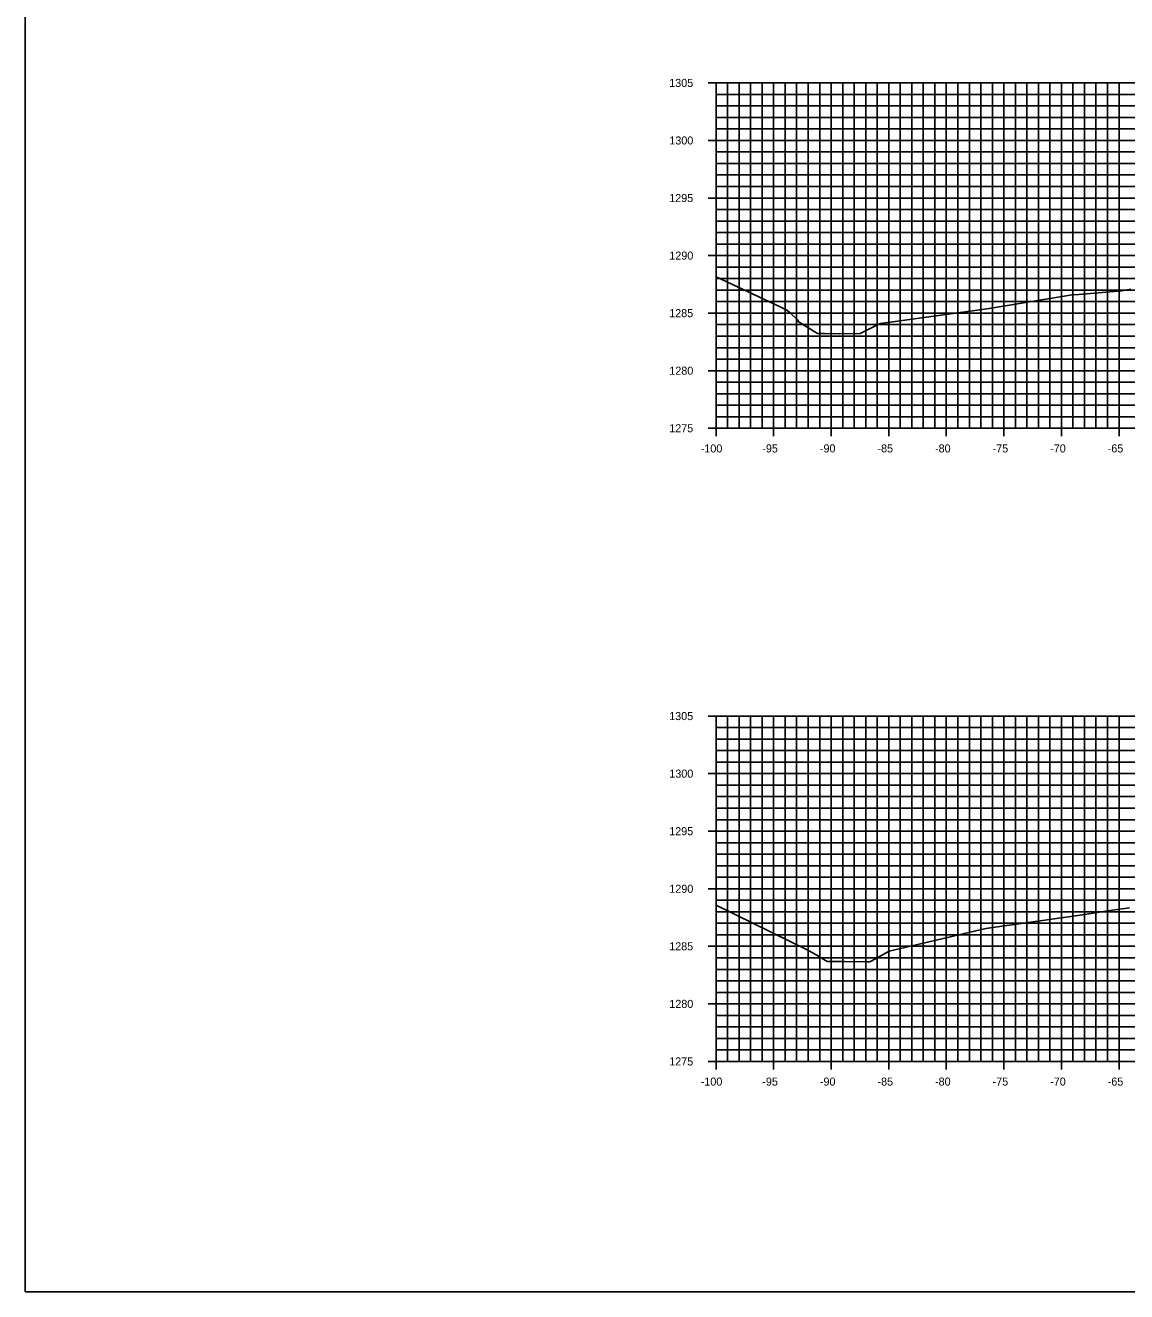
# Model space of a CAD drawing. Extents: x 674939 to 678919, y 750652 to 765176.
# Drawn here: x 678578.5 to 678674.2, y 755292.6 to 755402.6 of the extents above; entities that cross this region are included whole.
import ezdxf

# ---------------------------------------------------------------- set-up
doc = ezdxf.new("R2010")
doc.units = 0
for name, color, linetype in [('Level 10', 7, 'Continuous'), ('Level 20', 7, 'Continuous'), ('Level 4', 7, 'Continuous'), ('Level 8', 7, 'Continuous'), ('Level 9', 7, 'Continuous')]:
    doc.layers.add(name, color=color, linetype=linetype)

msp = doc.modelspace()

# ---------------------------------------------------------------- linework, layer by layer
at = {"layer": 'Level 10'}
for points in [[(678638.53, 755380.69), (678644.09, 755378.11), (678644.62, 755377.85), (678644.67, 755377.82), (678644.99, 755377.54), (678645.59, 755376.97), (678645.72, 755376.77), (678645.74, 755376.76), (678647.33, 755375.79), (678647.95, 755375.78), (678649.25, 755375.76), (678649.29, 755375.76), (678651.04, 755375.79), (678652.72, 755376.62), (678652.73, 755376.63), (678652.81, 755376.64), (678661.86, 755377.89), (678662.24, 755377.94), (678669.46, 755379.13), (678670.03, 755379.18), (678673.75, 755379.49), (678673.79, 755379.5), (678674.56, 755379.62)], [(678638.53, 755326.12), (678646.63, 755322.17), (678647.23, 755321.8), (678648.19, 755321.24), (678648.79, 755321.23), (678649.7, 755321.22), (678651.65, 755321.2), (678651.85, 755321.2), (678651.99, 755321.27), (678653.58, 755322.14), (678661.95, 755324.09), (678662.17, 755324.14), (678662.56, 755324.19), (678670.35, 755325.28), (678672.77, 755325.65), (678674.43, 755325.89)]]:
    msp.add_lwpolyline(points, dxfattribs=at)
at = {"layer": 'Level 20'}
for p, q in [((678638.53, 755397.55), (678838.53, 755397.55)), ((678638.53, 755367.55), (678638.53, 755397.55)), ((678639.53, 755367.55), (678639.53, 755397.55)), ((678640.53, 755367.55), (678640.53, 755397.55)), ((678641.53, 755367.55), (678641.53, 755397.55)), ((678642.53, 755367.55), (678642.53, 755397.55)), ((678643.53, 755367.55), (678643.53, 755397.55)), ((678644.53, 755367.55), (678644.53, 755397.55)), ((678645.53, 755367.55), (678645.53, 755397.55)), ((678646.53, 755367.55), (678646.53, 755397.55)), ((678647.53, 755367.55), (678647.53, 755397.55)), ((678648.53, 755367.55), (678648.53, 755397.55)), ((678649.53, 755367.55), (678649.53, 755397.55)), ((678650.53, 755367.55), (678650.53, 755397.55)), ((678651.53, 755367.55), (678651.53, 755397.55)), ((678652.53, 755367.55), (678652.53, 755397.55)), ((678653.53, 755367.55), (678653.53, 755397.55)), ((678654.53, 755367.55), (678654.53, 755397.55)), ((678655.53, 755367.55), (678655.53, 755397.55)), ((678656.53, 755367.55), (678656.53, 755397.55)), ((678657.53, 755367.55), (678657.53, 755397.55)), ((678658.53, 755367.55), (678658.53, 755397.55)), ((678659.53, 755367.55), (678659.53, 755397.55)), ((678660.53, 755367.55), (678660.53, 755397.55)), ((678661.53, 755367.55), (678661.53, 755397.55)), ((678662.53, 755367.55), (678662.53, 755397.55)), ((678663.53, 755367.55), (678663.53, 755397.55)), ((678664.53, 755367.55), (678664.53, 755397.55)), ((678665.53, 755367.55), (678665.53, 755397.55)), ((678666.53, 755367.55), (678666.53, 755397.55)), ((678667.53, 755367.55), (678667.53, 755397.55)), ((678668.53, 755367.55), (678668.53, 755397.55)), ((678669.53, 755367.55), (678669.53, 755397.55)), ((678670.53, 755367.55), (678670.53, 755397.55)), ((678671.53, 755367.55), (678671.53, 755397.55)), ((678672.53, 755367.55), (678672.53, 755397.55)), ((678673.53, 755367.55), (678673.53, 755397.55)), ((678638.53, 755396.55), (678838.53, 755396.55)), ((678638.53, 755395.55), (678838.53, 755395.55)), ((678638.53, 755394.55), (678838.53, 755394.55)), ((678638.53, 755393.55), (678838.53, 755393.55)), ((678638.53, 755392.55), (678838.53, 755392.55)), ((678638.53, 755391.55), (678838.53, 755391.55)), ((678638.53, 755390.55), (678838.53, 755390.55)), ((678638.53, 755389.55), (678838.53, 755389.55)), ((678638.53, 755388.55), (678838.53, 755388.55)), ((678638.53, 755387.55), (678838.53, 755387.55)), ((678638.53, 755386.55), (678838.53, 755386.55)), ((678638.53, 755385.55), (678838.53, 755385.55)), ((678638.53, 755384.55), (678838.53, 755384.55)), ((678638.53, 755383.55), (678838.53, 755383.55)), ((678638.53, 755382.55), (678838.53, 755382.55)), ((678638.53, 755381.55), (678838.53, 755381.55)), ((678638.53, 755380.55), (678838.53, 755380.55)), ((678638.53, 755379.55), (678838.53, 755379.55)), ((678638.53, 755378.55), (678838.53, 755378.55)), ((678638.53, 755377.55), (678838.53, 755377.55)), ((678638.53, 755376.55), (678838.53, 755376.55)), ((678638.53, 755375.55), (678838.53, 755375.55)), ((678638.53, 755374.55), (678838.53, 755374.55)), ((678638.53, 755373.55), (678838.53, 755373.55)), ((678638.53, 755372.55), (678838.53, 755372.55)), ((678638.53, 755371.55), (678838.53, 755371.55)), ((678638.53, 755370.55), (678838.53, 755370.55)), ((678638.53, 755369.55), (678838.53, 755369.55)), ((678638.53, 755368.55), (678838.53, 755368.55)), ((678638.53, 755367.55), (678838.53, 755367.55)), ((678638.53, 755342.55), (678838.53, 755342.55)), ((678638.53, 755312.55), (678638.53, 755342.55)), ((678639.53, 755312.55), (678639.53, 755342.55)), ((678640.53, 755312.55), (678640.53, 755342.55)), ((678641.53, 755312.55), (678641.53, 755342.55)), ((678642.53, 755312.55), (678642.53, 755342.55)), ((678643.53, 755312.55), (678643.53, 755342.55)), ((678644.53, 755312.55), (678644.53, 755342.55)), ((678645.53, 755312.55), (678645.53, 755342.55)), ((678646.53, 755312.55), (678646.53, 755342.55)), ((678647.53, 755312.55), (678647.53, 755342.55)), ((678648.53, 755312.55), (678648.53, 755342.55)), ((678649.53, 755312.55), (678649.53, 755342.55)), ((678650.53, 755312.55), (678650.53, 755342.55)), ((678651.53, 755312.55), (678651.53, 755342.55)), ((678652.53, 755312.55), (678652.53, 755342.55)), ((678653.53, 755312.55), (678653.53, 755342.55)), ((678654.53, 755312.55), (678654.53, 755342.55)), ((678655.53, 755312.55), (678655.53, 755342.55)), ((678656.53, 755312.55), (678656.53, 755342.55)), ((678657.53, 755312.55), (678657.53, 755342.55)), ((678658.53, 755312.55), (678658.53, 755342.55)), ((678659.53, 755312.55), (678659.53, 755342.55)), ((678660.53, 755312.55), (678660.53, 755342.55)), ((678661.53, 755312.55), (678661.53, 755342.55)), ((678662.53, 755312.55), (678662.53, 755342.55)), ((678663.53, 755312.55), (678663.53, 755342.55)), ((678664.53, 755312.55), (678664.53, 755342.55)), ((678665.53, 755312.55), (678665.53, 755342.55)), ((678666.53, 755312.55), (678666.53, 755342.55)), ((678667.53, 755312.55), (678667.53, 755342.55)), ((678668.53, 755312.55), (678668.53, 755342.55)), ((678669.53, 755312.55), (678669.53, 755342.55)), ((678670.53, 755312.55), (678670.53, 755342.55)), ((678671.53, 755312.55), (678671.53, 755342.55)), ((678672.53, 755312.55), (678672.53, 755342.55)), ((678673.53, 755312.55), (678673.53, 755342.55)), ((678638.53, 755341.55), (678838.53, 755341.55)), ((678638.53, 755340.55), (678838.53, 755340.55)), ((678638.53, 755339.55), (678838.53, 755339.55)), ((678638.53, 755338.55), (678838.53, 755338.55)), ((678638.53, 755337.55), (678838.53, 755337.55)), ((678638.53, 755336.55), (678838.53, 755336.55)), ((678638.53, 755335.55), (678838.53, 755335.55)), ((678638.53, 755334.55), (678838.53, 755334.55)), ((678638.53, 755333.55), (678838.53, 755333.55)), ((678638.53, 755332.55), (678838.53, 755332.55)), ((678638.53, 755331.55), (678838.53, 755331.55)), ((678638.53, 755330.55), (678838.53, 755330.55)), ((678638.53, 755329.55), (678838.53, 755329.55)), ((678638.53, 755328.55), (678838.53, 755328.55)), ((678638.53, 755327.55), (678838.53, 755327.55)), ((678638.53, 755326.55), (678838.53, 755326.55)), ((678638.53, 755325.55), (678838.53, 755325.55)), ((678638.53, 755324.55), (678838.53, 755324.55)), ((678638.53, 755323.55), (678838.53, 755323.55)), ((678638.53, 755322.55), (678838.53, 755322.55)), ((678638.53, 755321.55), (678838.53, 755321.55)), ((678638.53, 755320.55), (678838.53, 755320.55)), ((678638.53, 755319.55), (678838.53, 755319.55)), ((678638.53, 755318.55), (678838.53, 755318.55)), ((678638.53, 755317.55), (678838.53, 755317.55)), ((678638.53, 755316.55), (678838.53, 755316.55)), ((678638.53, 755315.55), (678838.53, 755315.55)), ((678638.53, 755314.55), (678838.53, 755314.55)), ((678638.53, 755313.55), (678838.53, 755313.55)), ((678638.53, 755312.55), (678838.53, 755312.55))]:
    msp.add_line(p, q, dxfattribs=at)
at = {"layer": 'Level 4'}
msp.add_lwpolyline([(678578.53, 755292.55), (678918.53, 755292.55), (678918.53, 755512.55), (678578.53, 755512.55)], close=True, dxfattribs=at)
at = {"layer": 'Level 8'}
for p, q in [((678637.83, 755397.55), (678639.23, 755397.55)), ((678638.53, 755367.55), (678638.53, 755397.55)), ((678638.53, 755396.55), (678638.88, 755396.55)), ((678638.53, 755395.55), (678638.88, 755395.55)), ((678638.53, 755394.55), (678638.88, 755394.55)), ((678638.53, 755393.55), (678638.88, 755393.55)), ((678637.83, 755392.55), (678639.23, 755392.55)), ((678638.53, 755391.55), (678638.88, 755391.55)), ((678638.53, 755390.55), (678638.88, 755390.55)), ((678638.53, 755389.55), (678638.88, 755389.55)), ((678638.53, 755388.55), (678638.88, 755388.55)), ((678637.83, 755387.55), (678639.23, 755387.55)), ((678638.53, 755386.55), (678638.88, 755386.55)), ((678638.53, 755385.55), (678638.88, 755385.55)), ((678638.53, 755384.55), (678638.88, 755384.55)), ((678638.53, 755383.55), (678638.88, 755383.55)), ((678637.83, 755382.55), (678639.23, 755382.55)), ((678638.53, 755381.55), (678638.88, 755381.55)), ((678638.53, 755380.55), (678638.88, 755380.55)), ((678638.53, 755379.55), (678638.88, 755379.55)), ((678638.53, 755378.55), (678638.88, 755378.55)), ((678637.83, 755377.55), (678639.23, 755377.55)), ((678638.53, 755376.55), (678638.88, 755376.55)), ((678638.53, 755375.55), (678638.88, 755375.55)), ((678638.53, 755374.55), (678638.88, 755374.55)), ((678638.53, 755373.55), (678638.88, 755373.55)), ((678637.83, 755372.55), (678639.23, 755372.55)), ((678638.53, 755371.55), (678638.88, 755371.55)), ((678638.53, 755370.55), (678638.88, 755370.55)), ((678638.53, 755369.55), (678638.88, 755369.55)), ((678638.53, 755368.55), (678638.88, 755368.55)), ((678638.53, 755366.85), (678638.53, 755368.25)), ((678643.53, 755366.85), (678643.53, 755368.25)), ((678648.53, 755366.85), (678648.53, 755368.25)), ((678653.53, 755366.85), (678653.53, 755368.25)), ((678658.53, 755366.85), (678658.53, 755368.25)), ((678663.53, 755366.85), (678663.53, 755368.25)), ((678668.53, 755366.85), (678668.53, 755368.25)), ((678673.53, 755366.85), (678673.53, 755368.25)), ((678637.83, 755367.55), (678639.23, 755367.55)), ((678638.53, 755367.55), (678838.53, 755367.55)), ((678637.83, 755342.55), (678639.23, 755342.55)), ((678638.53, 755312.55), (678638.53, 755342.55)), ((678638.53, 755341.55), (678638.88, 755341.55)), ((678638.53, 755340.55), (678638.88, 755340.55)), ((678638.53, 755339.55), (678638.88, 755339.55)), ((678638.53, 755338.55), (678638.88, 755338.55)), ((678637.83, 755337.55), (678639.23, 755337.55)), ((678638.53, 755336.55), (678638.88, 755336.55)), ((678638.53, 755335.55), (678638.88, 755335.55)), ((678638.53, 755334.55), (678638.88, 755334.55)), ((678638.53, 755333.55), (678638.88, 755333.55)), ((678637.83, 755332.55), (678639.23, 755332.55)), ((678638.53, 755331.55), (678638.88, 755331.55)), ((678638.53, 755330.55), (678638.88, 755330.55)), ((678638.53, 755329.55), (678638.88, 755329.55)), ((678638.53, 755328.55), (678638.88, 755328.55)), ((678637.83, 755327.55), (678639.23, 755327.55)), ((678638.53, 755326.55), (678638.88, 755326.55)), ((678638.53, 755325.55), (678638.88, 755325.55)), ((678638.53, 755324.55), (678638.88, 755324.55)), ((678638.53, 755323.55), (678638.88, 755323.55)), ((678637.83, 755322.55), (678639.23, 755322.55)), ((678638.53, 755321.55), (678638.88, 755321.55)), ((678638.53, 755320.55), (678638.88, 755320.55)), ((678638.53, 755319.55), (678638.88, 755319.55)), ((678638.53, 755318.55), (678638.88, 755318.55)), ((678637.83, 755317.55), (678639.23, 755317.55)), ((678638.53, 755316.55), (678638.88, 755316.55)), ((678638.53, 755315.55), (678638.88, 755315.55)), ((678638.53, 755314.55), (678638.88, 755314.55)), ((678638.53, 755313.55), (678638.88, 755313.55)), ((678638.53, 755311.85), (678638.53, 755313.25)), ((678643.53, 755311.85), (678643.53, 755313.25)), ((678648.53, 755311.85), (678648.53, 755313.25)), ((678653.53, 755311.85), (678653.53, 755313.25)), ((678658.53, 755311.85), (678658.53, 755313.25)), ((678663.53, 755311.85), (678663.53, 755313.25)), ((678668.53, 755311.85), (678668.53, 755313.25)), ((678673.53, 755311.85), (678673.53, 755313.25)), ((678637.83, 755312.55), (678639.23, 755312.55)), ((678638.53, 755312.55), (678838.53, 755312.55))]:
    msp.add_line(p, q, dxfattribs=at)

# ---------------------------------------------------------------- texts
at = {"layer": 'Level 9'}
for s, p in [('1305', (678634.46, 755397.2)), ('1300', (678634.47, 755392.2)), ('1295', (678634.46, 755387.2)), ('1290', (678634.47, 755382.2)), ('1285', (678634.46, 755377.2)), ('1280', (678634.47, 755372.2)), ('1275', (678634.46, 755367.2)), ('-100', (678637.2, 755365.45)), ('-95', (678642.55, 755365.45)), ('-90', (678647.55, 755365.45)), ('-85', (678652.55, 755365.45)), ('-80', (678657.55, 755365.45)), ('-75', (678662.55, 755365.45)), ('-70', (678667.55, 755365.45)), ('-65', (678672.55, 755365.45)), ('1305', (678634.46, 755342.2)), ('1300', (678634.47, 755337.2)), ('1295', (678634.46, 755332.2)), ('1290', (678634.47, 755327.2)), ('1285', (678634.46, 755322.2)), ('1280', (678634.47, 755317.2)), ('1275', (678634.46, 755312.2)), ('-100', (678637.2, 755310.45)), ('-95', (678642.55, 755310.45)), ('-90', (678647.55, 755310.45)), ('-85', (678652.55, 755310.45)), ('-80', (678657.55, 755310.45)), ('-75', (678662.55, 755310.45)), ('-70', (678667.55, 755310.45)), ('-65', (678672.55, 755310.45))]:
    msp.add_text(s, height=0.7, dxfattribs=at).set_placement(p)

doc.saveas('drawing.dxf')
